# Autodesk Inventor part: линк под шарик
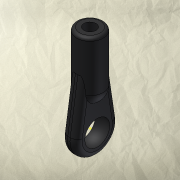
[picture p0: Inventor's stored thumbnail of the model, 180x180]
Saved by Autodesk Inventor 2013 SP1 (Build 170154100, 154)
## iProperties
Created: 2012-02
Part Number: линк под шарик
Material: Allgemein
Document SubType Name: Modeling
Designer: WH
Density: 1 g/cm^3
ipwModelExtentsX: 4.4
ipwModelExtentsY: 7
ipwModelExtentsZ: 18.5
ipwMass: 0.0
ipwArea: 0 m^2
ipwVolume: 0
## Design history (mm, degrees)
feature "Basis1"
feature "Fläche verschieben1" dims "d0" = 0.5
workpoint "Arbeitspunkt1"
  workaxis "Arbeitsachse1"
node "линк под шарик"
